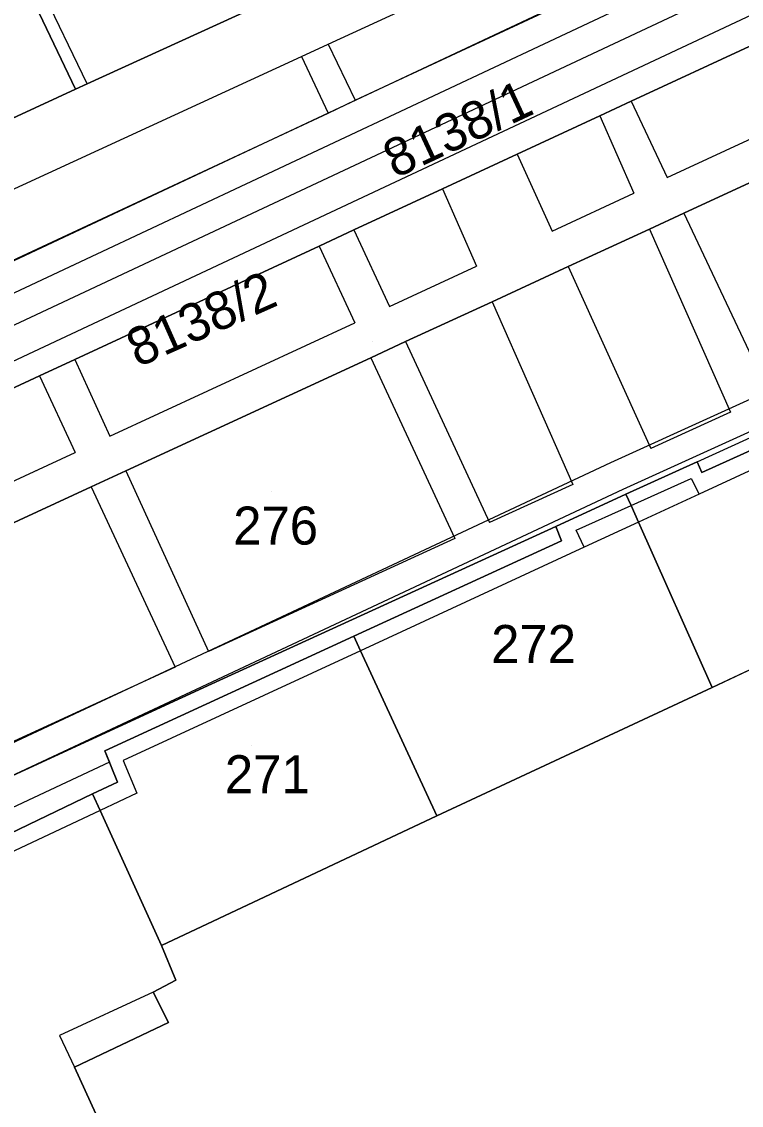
# Model space of a CAD drawing. Extents: x -264070 to -262271, y -1238894 to -1238141.
# Drawn here: x -263591.6 to -263553.8, y -1238608.4 to -1238551.4 of the extents above; entities that cross this region are included whole.
import ezdxf

# ---------------------------------------------------------------- set-up
doc = ezdxf.new("R2010")
doc.units = 0
for name, color, linetype in [('body_kn', 7, 'Continuous'), ('kladpar_druhypozemkov', 7, 'Continuous'), ('kladpar_hranice', 7, 'Continuous'), ('kladpar_parcelnecisla', 7, 'Continuous'), ('kladpar_plochy', 7, 'Continuous'), ('tarchy_linie', 7, 'Continuous'), ('zappar_hrandruhpozemk', 7, 'Continuous')]:
    doc.layers.add(name, color=color, linetype=linetype)

msp = doc.modelspace()

# ---------------------------------------------------------------- linework, layer by layer
at = {"layer": 'body_kn'}
for p, q in [((-263575.5, -1238552.57), (-263575.5, -1238552.57)), ((-263575.5, -1238552.57), (-263575.5, -1238552.57)), ((-263576.9, -1238553.22), (-263576.9, -1238553.22)), ((-263588.16, -1238554.66), (-263588.16, -1238554.66)), ((-263588.16, -1238554.66), (-263588.16, -1238554.66)), ((-263588.78, -1238554.94), (-263588.78, -1238554.94)), ((-263574.07, -1238555.52), (-263574.07, -1238555.52)), ((-263559.56, -1238555.56), (-263559.56, -1238555.56)), ((-263559.56, -1238555.56), (-263559.56, -1238555.56)), ((-263575.5, -1238556.19), (-263575.5, -1238556.19)), ((-263575.5, -1238556.19), (-263575.5, -1238556.19)), ((-263561.21, -1238556.33), (-263561.21, -1238556.33)), ((-263561.21, -1238556.33), (-263561.21, -1238556.33)), ((-263565.55, -1238558.35), (-263565.55, -1238558.35)), ((-263565.55, -1238558.35), (-263565.55, -1238558.35)), ((-263557.67, -1238559.58), (-263557.67, -1238559.58)), ((-263557.67, -1238559.58), (-263557.67, -1238559.58)), ((-263569.48, -1238560.18), (-263569.48, -1238560.18)), ((-263569.48, -1238560.18), (-263569.48, -1238560.18)), ((-263559.42, -1238560.4), (-263559.42, -1238560.4)), ((-263556.79, -1238561.45), (-263556.79, -1238561.45)), ((-263556.79, -1238561.45), (-263556.79, -1238561.45)), ((-263574.14, -1238562.34), (-263574.14, -1238562.34)), ((-263574.14, -1238562.34), (-263574.14, -1238562.34)), ((-263563.71, -1238562.4), (-263563.71, -1238562.4)), ((-263563.71, -1238562.4), (-263563.71, -1238562.4)), ((-263558.59, -1238562.29), (-263558.59, -1238562.29)), ((-263558.59, -1238562.29), (-263558.59, -1238562.29)), ((-263575.96, -1238563.19), (-263575.96, -1238563.19)), ((-263575.96, -1238563.19), (-263575.96, -1238563.19)), ((-263567.69, -1238564.25), (-263567.69, -1238564.25)), ((-263562.87, -1238564.27), (-263562.87, -1238564.27)), ((-263562.87, -1238564.27), (-263562.87, -1238564.27)), ((-263572.27, -1238566.37), (-263572.27, -1238566.37)), ((-263572.27, -1238566.37), (-263572.27, -1238566.37)), ((-263566.87, -1238566.12), (-263566.87, -1238566.12)), ((-263566.87, -1238566.12), (-263566.87, -1238566.12)), ((-263574.09, -1238567.22), (-263574.09, -1238567.22)), ((-263571.42, -1238568.21), (-263571.42, -1238568.21)), ((-263571.42, -1238568.21), (-263571.42, -1238568.21)), ((-263588.82, -1238569.16), (-263588.82, -1238569.16)), ((-263588.82, -1238569.16), (-263588.82, -1238569.16)), ((-263573.25, -1238569.06), (-263573.25, -1238569.06)), ((-263573.25, -1238569.06), (-263573.25, -1238569.06)), ((-263590.67, -1238570.02), (-263590.67, -1238570.02)), ((-263590.67, -1238570.02), (-263590.67, -1238570.02)), ((-263554.34, -1238571.92), (-263554.34, -1238571.92)), ((-263554.34, -1238571.92), (-263554.34, -1238571.92)), ((-263586.97, -1238573.19), (-263586.97, -1238573.19)), ((-263586.97, -1238573.19), (-263586.97, -1238573.19)), ((-263588.8, -1238574.04), (-263588.8, -1238574.04)), ((-263558.52, -1238573.84), (-263558.52, -1238573.84)), ((-263560.64, -1238574.57), (-263560.64, -1238574.57)), ((-263556.1, -1238574.53), (-263556.1, -1238574.53)), ((-263556.1, -1238574.53), (-263556.1, -1238574.53)), ((-263586.14, -1238575.01), (-263586.14, -1238575.01)), ((-263586.14, -1238575.01), (-263586.14, -1238575.01)), ((-263555.84, -1238575.1), (-263555.84, -1238575.1)), ((-263562.63, -1238575.73), (-263562.63, -1238575.73)), ((-263562.63, -1238575.73), (-263562.63, -1238575.73)), ((-263556.4, -1238575.42), (-263556.4, -1238575.42)), ((-263587.96, -1238575.85), (-263587.96, -1238575.85)), ((-263587.96, -1238575.85), (-263587.96, -1238575.85)), ((-263559.99, -1238575.98), (-263559.99, -1238575.98)), ((-263559.84, -1238576.24), (-263559.84, -1238576.24)), ((-263555.99, -1238576.24), (-263555.99, -1238576.24)), ((-263559.57, -1238576.84), (-263559.57, -1238576.84)), ((-263559.57, -1238576.84), (-263559.57, -1238576.84)), ((-263567.01, -1238577.73), (-263567.01, -1238577.73)), ((-263563.53, -1238577.94), (-263563.53, -1238577.94)), ((-263559.18, -1238577.71), (-263559.18, -1238577.71)), ((-263559.18, -1238577.71), (-263559.18, -1238577.71)), ((-263568.84, -1238578.57), (-263568.84, -1238578.57)), ((-263568.84, -1238578.57), (-263568.84, -1238578.57)), ((-263562.46, -1238578.13), (-263562.46, -1238578.13)), ((-263563.23, -1238578.69), (-263563.23, -1238578.69)), ((-263563.23, -1238578.69), (-263563.23, -1238578.69)), ((-263562.04, -1238579.03), (-263562.04, -1238579.03)), ((-263562.04, -1238579.03), (-263562.04, -1238579.03)), ((-263574.15, -1238583.71), (-263574.15, -1238583.71)), ((-263574.15, -1238583.71), (-263574.15, -1238583.71)), ((-263581.78, -1238584.52), (-263581.78, -1238584.52)), ((-263573.79, -1238584.47), (-263573.79, -1238584.47)), ((-263573.79, -1238584.47), (-263573.79, -1238584.47)), ((-263583.54, -1238585.33), (-263583.54, -1238585.33)), ((-263583.54, -1238585.33), (-263583.54, -1238585.33)), ((-263581.62, -1238586.21), (-263581.62, -1238586.21)), ((-263555.3, -1238586.4), (-263555.3, -1238586.4)), ((-263587.23, -1238589.73), (-263587.23, -1238589.73)), ((-263586.99, -1238590.34), (-263586.99, -1238590.34)), ((-263586.27, -1238590.25), (-263586.27, -1238590.25)), ((-263586.58, -1238591.38), (-263586.58, -1238591.38)), ((-263587.89, -1238592), (-263587.89, -1238592)), ((-263587.89, -1238592), (-263587.89, -1238592)), ((-263585.56, -1238591.96), (-263585.56, -1238591.96)), ((-263587.49, -1238592.87), (-263587.49, -1238592.87)), ((-263587.49, -1238592.87), (-263587.49, -1238592.87)), ((-263569.78, -1238593.15), (-263569.78, -1238593.15)), ((-263584.26, -1238599.97), (-263584.26, -1238599.97)), ((-263583.5, -1238601.81), (-263583.5, -1238601.81)), ((-263584.7, -1238602.44), (-263584.7, -1238602.44)), ((-263584.7, -1238602.44), (-263584.7, -1238602.44)), ((-263583.89, -1238604.03), (-263583.89, -1238604.03)), ((-263589.62, -1238604.71), (-263589.62, -1238604.71)), ((-263588.84, -1238606.37), (-263588.84, -1238606.37))]:
    msp.add_line(p, q, dxfattribs=at)
at = {"layer": 'kladpar_druhypozemkov'}
for p, q in [((-263569.16, -1238556.97), (-263569.16, -1238556.97)), ((-263573.18, -1238568.23), (-263573.18, -1238568.23)), ((-263578.5, -1238576.11), (-263578.5, -1238576.11)), ((-263564.67, -1238582.88), (-263564.67, -1238582.88)), ((-263579.55, -1238589.47), (-263579.55, -1238589.47))]:
    msp.add_line(p, q, dxfattribs=at)
at = {"layer": 'kladpar_hranice'}
msp.add_line((-263555.3, -1238586.4), (-263540.75, -1238579.58), dxfattribs=at)
for points in [[(-263581.52, -1238543.43), (-263580.02, -1238542.73), (-263571.24, -1238538.67), (-263568.91, -1238539.22), (-263566.4, -1238544.65), (-263566.9, -1238544.88), (-263576.88, -1238549.47), (-263578.37, -1238550.16), (-263588.16, -1238554.66), (-263588.78, -1238554.94), (-263591.26, -1238549.75), (-263590.26, -1238547.47), (-263581.52, -1238543.43)], [(-263599.97, -1238547.5), (-263602.14, -1238542.74), (-263594.34, -1238539.11), (-263590.26, -1238547.47), (-263591.26, -1238549.75), (-263588.78, -1238554.94), (-263593.04, -1238556.9), (-263592.86, -1238557.8), (-263601.47, -1238561.82), (-263601.83, -1238561.04), (-263606.21, -1238563.07), (-263606.45, -1238562.5), (-263609.49, -1238563.91), (-263614.11, -1238554.1), (-263599.97, -1238547.5)], [(-263633.48, -1238575.09), (-263609.49, -1238563.91), (-263606.45, -1238562.5), (-263606.21, -1238563.07), (-263601.83, -1238561.04), (-263601.47, -1238561.82), (-263592.86, -1238557.8), (-263593.04, -1238556.9), (-263588.78, -1238554.94), (-263588.16, -1238554.66), (-263578.37, -1238550.16), (-263576.88, -1238549.47), (-263566.9, -1238544.88)], [(-263546.69, -1238549.58), (-263559.56, -1238555.56), (-263561.21, -1238556.33), (-263565.55, -1238558.35), (-263569.48, -1238560.18), (-263574.14, -1238562.34), (-263575.96, -1238563.19), (-263588.82, -1238569.16), (-263590.67, -1238570.02), (-263602.8, -1238575.66), (-263604.49, -1238576.44), (-263620.68, -1238583.97)], [(-263569.48, -1238560.18), (-263565.55, -1238558.35), (-263561.21, -1238556.33), (-263559.56, -1238555.56), (-263546.69, -1238549.58)], [(-263543.92, -1238555.51), (-263556.79, -1238561.45), (-263558.59, -1238562.29), (-263562.87, -1238564.27), (-263566.87, -1238566.12), (-263571.42, -1238568.21), (-263573.25, -1238569.06), (-263586.14, -1238575.01), (-263587.96, -1238575.85), (-263600.06, -1238581.44), (-263601.77, -1238582.22), (-263617.99, -1238589.72), (-263613.57, -1238599.13), (-263612.87, -1238600.61), (-263614.71, -1238601.49), (-263620.74, -1238604.27)], [(-263544.99, -1238570.18), (-263555.84, -1238575.1), (-263556.1, -1238574.53), (-263559.84, -1238576.24), (-263563.53, -1238577.94), (-263581.62, -1238586.21), (-263612.87, -1238600.61), (-263613.57, -1238599.13), (-263617.99, -1238589.72), (-263601.77, -1238582.22), (-263600.06, -1238581.44), (-263587.96, -1238575.85), (-263586.14, -1238575.01), (-263573.25, -1238569.06), (-263571.42, -1238568.21), (-263566.87, -1238566.12), (-263562.87, -1238564.27), (-263558.59, -1238562.29), (-263556.79, -1238561.45), (-263543.92, -1238555.51)], [(-263620.68, -1238583.97), (-263604.49, -1238576.44), (-263602.8, -1238575.66), (-263590.67, -1238570.02), (-263588.82, -1238569.16), (-263575.96, -1238563.19), (-263574.14, -1238562.34), (-263569.48, -1238560.18)], [(-263544.99, -1238570.18), (-263544.63, -1238570.98), (-263540.75, -1238579.58), (-263555.3, -1238586.4), (-263559.18, -1238577.71), (-263559.57, -1238576.84), (-263559.84, -1238576.24), (-263556.1, -1238574.53), (-263555.84, -1238575.1), (-263544.99, -1238570.18)], [(-263563.23, -1238578.69), (-263563.53, -1238577.94), (-263559.84, -1238576.24), (-263559.57, -1238576.84), (-263559.18, -1238577.71), (-263555.3, -1238586.4), (-263569.78, -1238593.15), (-263573.79, -1238584.47), (-263574.15, -1238583.71), (-263563.23, -1238578.69)], [(-263600.25, -1238627.45), (-263612.87, -1238600.61), (-263581.62, -1238586.21), (-263563.53, -1238577.94), (-263563.23, -1238578.69), (-263574.15, -1238583.71), (-263587.23, -1238589.73), (-263586.58, -1238591.38), (-263587.89, -1238592), (-263603.77, -1238599.64), (-263596.34, -1238615.99)], [(-263574.15, -1238583.71), (-263573.79, -1238584.47), (-263569.78, -1238593.15), (-263584.26, -1238599.97), (-263587.49, -1238592.87), (-263587.89, -1238592), (-263586.58, -1238591.38), (-263587.23, -1238589.73), (-263574.15, -1238583.71)], [(-263586.31, -1238611.9), (-263588.84, -1238606.37), (-263583.89, -1238604.03), (-263584.7, -1238602.44), (-263583.5, -1238601.81), (-263584.26, -1238599.97), (-263569.78, -1238593.15), (-263555.3, -1238586.4)], [(-263587.89, -1238592), (-263587.49, -1238592.87), (-263584.26, -1238599.97), (-263583.5, -1238601.81), (-263584.7, -1238602.44), (-263583.89, -1238604.03), (-263588.84, -1238606.37), (-263586.31, -1238611.9), (-263595.09, -1238616.19), (-263598.25, -1238617.75), (-263598.78, -1238618), (-263599.1, -1238617.33), (-263596.34, -1238615.99), (-263603.77, -1238599.64), (-263587.89, -1238592)]]:
    msp.add_lwpolyline(points, dxfattribs=at)
at = {"layer": 'kladpar_plochy'}
for p, q in [((-263555.3, -1238586.4), (-263540.75, -1238579.58)), ((-263569.78, -1238593.15), (-263555.3, -1238586.4)), ((-263584.26, -1238599.97), (-263569.78, -1238593.15)), ((-263583.5, -1238601.81), (-263584.26, -1238599.97)), ((-263584.7, -1238602.44), (-263583.5, -1238601.81)), ((-263583.89, -1238604.03), (-263584.7, -1238602.44)), ((-263588.84, -1238606.37), (-263583.89, -1238604.03)), ((-263586.31, -1238611.9), (-263588.84, -1238606.37))]:
    msp.add_line(p, q, dxfattribs=at)
for points in [[(-263581.52, -1238543.43), (-263580.02, -1238542.73), (-263571.24, -1238538.67), (-263568.91, -1238539.22), (-263566.4, -1238544.65), (-263566.9, -1238544.88), (-263576.88, -1238549.47), (-263578.37, -1238550.16), (-263588.16, -1238554.66), (-263588.78, -1238554.94), (-263591.26, -1238549.75), (-263590.26, -1238547.47)], [(-263599.97, -1238547.5), (-263602.14, -1238542.74), (-263594.34, -1238539.11), (-263590.26, -1238547.47), (-263591.26, -1238549.75), (-263588.78, -1238554.94), (-263593.04, -1238556.9), (-263592.86, -1238557.8), (-263601.47, -1238561.82), (-263601.83, -1238561.04), (-263606.21, -1238563.07), (-263606.45, -1238562.5), (-263609.49, -1238563.91), (-263614.11, -1238554.1)], [(-263544.99, -1238570.18), (-263544.63, -1238570.98), (-263540.75, -1238579.58), (-263555.3, -1238586.4), (-263559.18, -1238577.71), (-263559.57, -1238576.84), (-263559.84, -1238576.24), (-263556.1, -1238574.53), (-263555.84, -1238575.1)], [(-263563.23, -1238578.69), (-263563.53, -1238577.94), (-263559.84, -1238576.24), (-263559.57, -1238576.84), (-263559.18, -1238577.71), (-263555.3, -1238586.4), (-263569.78, -1238593.15), (-263573.79, -1238584.47), (-263574.15, -1238583.71)], [(-263574.15, -1238583.71), (-263573.79, -1238584.47), (-263569.78, -1238593.15), (-263584.26, -1238599.97), (-263587.49, -1238592.87), (-263587.89, -1238592), (-263586.58, -1238591.38), (-263587.23, -1238589.73)], [(-263587.89, -1238592), (-263587.49, -1238592.87), (-263584.26, -1238599.97), (-263583.5, -1238601.81), (-263584.7, -1238602.44), (-263583.89, -1238604.03), (-263588.84, -1238606.37), (-263586.31, -1238611.9), (-263595.09, -1238616.19), (-263598.25, -1238617.75), (-263598.78, -1238618), (-263599.1, -1238617.33), (-263596.34, -1238615.99), (-263603.77, -1238599.64)]]:
    msp.add_lwpolyline(points, close=True, dxfattribs=at)
for points in [[(-263633.48, -1238575.09), (-263609.49, -1238563.91), (-263606.45, -1238562.5), (-263606.21, -1238563.07), (-263601.83, -1238561.04), (-263601.47, -1238561.82), (-263592.86, -1238557.8), (-263593.04, -1238556.9), (-263588.78, -1238554.94), (-263588.16, -1238554.66), (-263578.37, -1238550.16), (-263576.88, -1238549.47), (-263566.9, -1238544.88), (-263566.4, -1238544.65), (-263561.84, -1238542.55), (-263561.51, -1238543.33), (-263552.99, -1238539.42)], [(-263620.68, -1238583.97), (-263604.49, -1238576.44), (-263602.8, -1238575.66), (-263590.67, -1238570.02), (-263588.82, -1238569.16), (-263575.96, -1238563.19), (-263574.14, -1238562.34), (-263569.48, -1238560.18), (-263565.55, -1238558.35), (-263561.21, -1238556.33), (-263559.56, -1238555.56), (-263546.69, -1238549.58)], [(-263546.69, -1238549.58), (-263559.56, -1238555.56), (-263561.21, -1238556.33), (-263565.55, -1238558.35), (-263569.48, -1238560.18), (-263574.14, -1238562.34), (-263575.96, -1238563.19), (-263588.82, -1238569.16), (-263590.67, -1238570.02), (-263602.8, -1238575.66), (-263604.49, -1238576.44), (-263620.68, -1238583.97)], [(-263543.92, -1238555.51), (-263556.79, -1238561.45), (-263558.59, -1238562.29), (-263562.87, -1238564.27), (-263566.87, -1238566.12), (-263571.42, -1238568.21), (-263573.25, -1238569.06), (-263586.14, -1238575.01), (-263587.96, -1238575.85), (-263600.06, -1238581.44), (-263601.77, -1238582.22), (-263617.99, -1238589.72), (-263613.57, -1238599.13), (-263612.87, -1238600.61), (-263614.71, -1238601.49), (-263620.74, -1238604.27)], [(-263544.99, -1238570.18), (-263555.84, -1238575.1), (-263556.1, -1238574.53), (-263559.84, -1238576.24), (-263563.53, -1238577.94), (-263581.62, -1238586.21), (-263612.87, -1238600.61), (-263613.57, -1238599.13), (-263617.99, -1238589.72), (-263601.77, -1238582.22), (-263600.06, -1238581.44), (-263587.96, -1238575.85), (-263586.14, -1238575.01), (-263573.25, -1238569.06), (-263571.42, -1238568.21), (-263566.87, -1238566.12), (-263562.87, -1238564.27), (-263558.59, -1238562.29), (-263556.79, -1238561.45), (-263543.92, -1238555.51)], [(-263600.25, -1238627.45), (-263612.87, -1238600.61), (-263581.62, -1238586.21), (-263563.53, -1238577.94), (-263563.23, -1238578.69), (-263574.15, -1238583.71), (-263587.23, -1238589.73), (-263586.58, -1238591.38), (-263587.89, -1238592), (-263603.77, -1238599.64), (-263596.34, -1238615.99)]]:
    msp.add_lwpolyline(points, dxfattribs=at)
at = {"layer": 'tarchy_linie'}
msp.add_line((-263515.63, -1238529.75), (-263622.44, -1238579.95), dxfattribs=at)
for points in [[(-263623.06, -1238578.54), (-263516.27, -1238528.34), (-263516.2, -1238528.48), (-263515.63, -1238529.75), (-263514.94, -1238531.28), (-263514.24, -1238532.83), (-263550.68, -1238549.82), (-263593.84, -1238570.08), (-263621.18, -1238582.83), (-263621.86, -1238581.27), (-263622.44, -1238579.95), (-263623.06, -1238578.54)], [(-263514.94, -1238531.28), (-263551.4, -1238548.28), (-263594.56, -1238568.54), (-263621.86, -1238581.27)], [(-263629.82, -1238588.19), (-263620.16, -1238603.28), (-263610.33, -1238597.86), (-263560.64, -1238574.57), (-263510.77, -1238551.88), (-263499.93, -1238574.86)], [(-263651.39, -1238621.79), (-263634.28, -1238612.66), (-263633.98, -1238612.67), (-263633.77, -1238612.82), (-263624.03, -1238608.06), (-263624.37, -1238607.36), (-263623.97, -1238607.16), (-263609.63, -1238599.24), (-263559.99, -1238575.98), (-263511.52, -1238553.93), (-263501.34, -1238575.51)], [(-263502.75, -1238576.17), (-263512.27, -1238555.98), (-263529.14, -1238563.65), (-263529.36, -1238563.17), (-263530, -1238563.42), (-263544.99, -1238570.18), (-263555.84, -1238575.1), (-263556.1, -1238574.53), (-263559.84, -1238576.24), (-263563.53, -1238577.94), (-263563.23, -1238578.69), (-263574.15, -1238583.71), (-263587.23, -1238589.73), (-263586.99, -1238590.34), (-263607.56, -1238599.98), (-263594.13, -1238627.86)]]:
    msp.add_lwpolyline(points, dxfattribs=at)
at = {"layer": 'zappar_hrandruhpozemk'}
for p, q in [((-263556.1, -1238574.53), (-263499.77, -1238548.96)), ((-263575.5, -1238552.57), (-263574.07, -1238555.52)), ((-263602.42, -1238564.97), (-263576.9, -1238553.22)), ((-263576.9, -1238553.22), (-263575.5, -1238556.19)), ((-263557.67, -1238559.58), (-263544.8, -1238553.61)), ((-263559.56, -1238555.56), (-263557.67, -1238559.58)), ((-263615.54, -1238574.9), (-263575.5, -1238556.19)), ((-263561.21, -1238556.33), (-263559.42, -1238560.4)), ((-263565.55, -1238558.35), (-263563.71, -1238562.4)), ((-263569.48, -1238560.18), (-263567.69, -1238564.25)), ((-263563.71, -1238562.4), (-263559.42, -1238560.4)), ((-263556.79, -1238561.45), (-263552.31, -1238570.98)), ((-263574.14, -1238562.34), (-263572.27, -1238566.37)), ((-263558.59, -1238562.29), (-263554.34, -1238571.92)), ((-263575.96, -1238563.19), (-263574.09, -1238567.22)), ((-263572.27, -1238566.37), (-263567.69, -1238564.25)), ((-263562.87, -1238564.27), (-263558.52, -1238573.84)), ((-263566.87, -1238566.12), (-263562.63, -1238575.73)), ((-263586.97, -1238573.19), (-263574.09, -1238567.22)), ((-263571.42, -1238568.21), (-263567.01, -1238577.73)), ((-263588.82, -1238569.16), (-263586.97, -1238573.19)), ((-263573.25, -1238569.06), (-263568.84, -1238578.57)), ((-263590.67, -1238570.02), (-263588.8, -1238574.04)), ((-263554.34, -1238571.92), (-263558.52, -1238573.84)), ((-263600.9, -1238579.66), (-263588.8, -1238574.04)), ((-263586.14, -1238575.01), (-263581.78, -1238584.52)), ((-263562.63, -1238575.73), (-263567.01, -1238577.73)), ((-263587.96, -1238575.85), (-263583.54, -1238585.33)), ((-263568.84, -1238578.57), (-263581.78, -1238584.52)), ((-263573.79, -1238584.47), (-263586.27, -1238590.25)), ((-263583.54, -1238585.33), (-263595.57, -1238590.86)), ((-263587.49, -1238592.87), (-263602.54, -1238599.95)), ((-263584.7, -1238602.44), (-263589.62, -1238604.71)), ((-263589.62, -1238604.71), (-263588.84, -1238606.37))]:
    msp.add_line(p, q, dxfattribs=at)
for points in [[(-263576.9, -1238553.22), (-263575.5, -1238552.57), (-263556.88, -1238543.99), (-263555.49, -1238543.34), (-263549.8, -1238540.72), (-263549.38, -1238538.95), (-263518.17, -1238524.44)], [(-263575.5, -1238556.19), (-263574.07, -1238555.52), (-263555.62, -1238546.9), (-263554.16, -1238546.21)], [(-263588.16, -1238554.66), (-263590.61, -1238549.59), (-263589.61, -1238547.73)], [(-263544.63, -1238570.98), (-263555.99, -1238576.24), (-263559.18, -1238577.71)], [(-263559.57, -1238576.84), (-263556.4, -1238575.42), (-263555.99, -1238576.24)], [(-263562.04, -1238579.03), (-263562.46, -1238578.13), (-263559.57, -1238576.84)], [(-263559.18, -1238577.71), (-263562.04, -1238579.03), (-263573.79, -1238584.47)], [(-263586.27, -1238590.25), (-263585.56, -1238591.96), (-263587.49, -1238592.87)]]:
    msp.add_lwpolyline(points, dxfattribs=at)

# ---------------------------------------------------------------- texts
at = {"layer": 'kladpar_parcelnecisla'}
for s, rotation, p in [('8138/1', 25, (-263571.981, -1238559.65)), ('8138/2', 24, (-263585.51, -1238569.592))]:
    msp.add_text(s, height=2, rotation=rotation, dxfattribs=at).set_placement(p)
for s, p in [('276', (-263580.488, -1238578.89)), ('272', (-263566.925, -1238585.12)), ('271', (-263580.929, -1238591.97))]:
    msp.add_text(s, height=2, dxfattribs=at).set_placement(p)

doc.saveas('drawing.dxf')
